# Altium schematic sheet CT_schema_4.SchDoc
size 511 x 385 mm
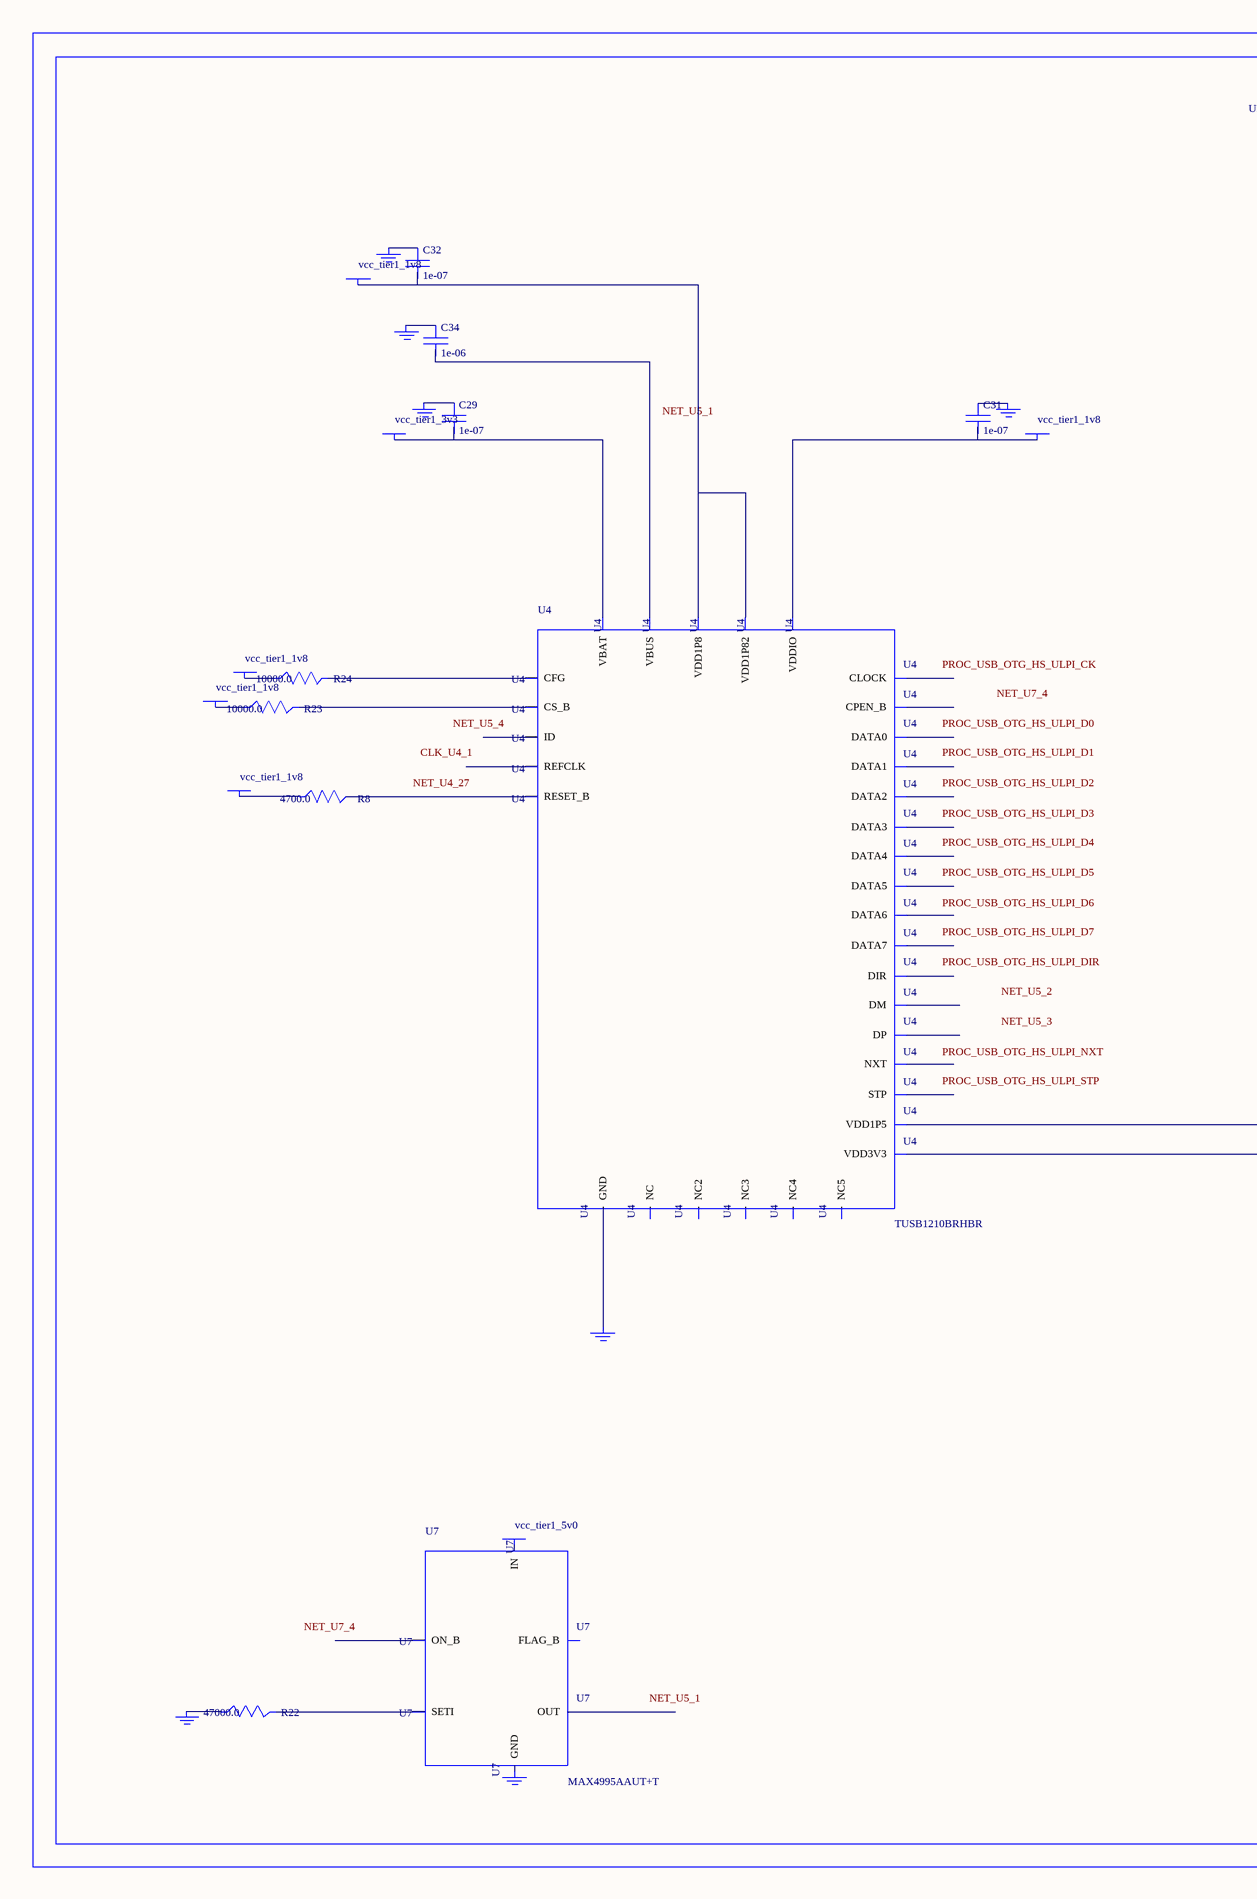
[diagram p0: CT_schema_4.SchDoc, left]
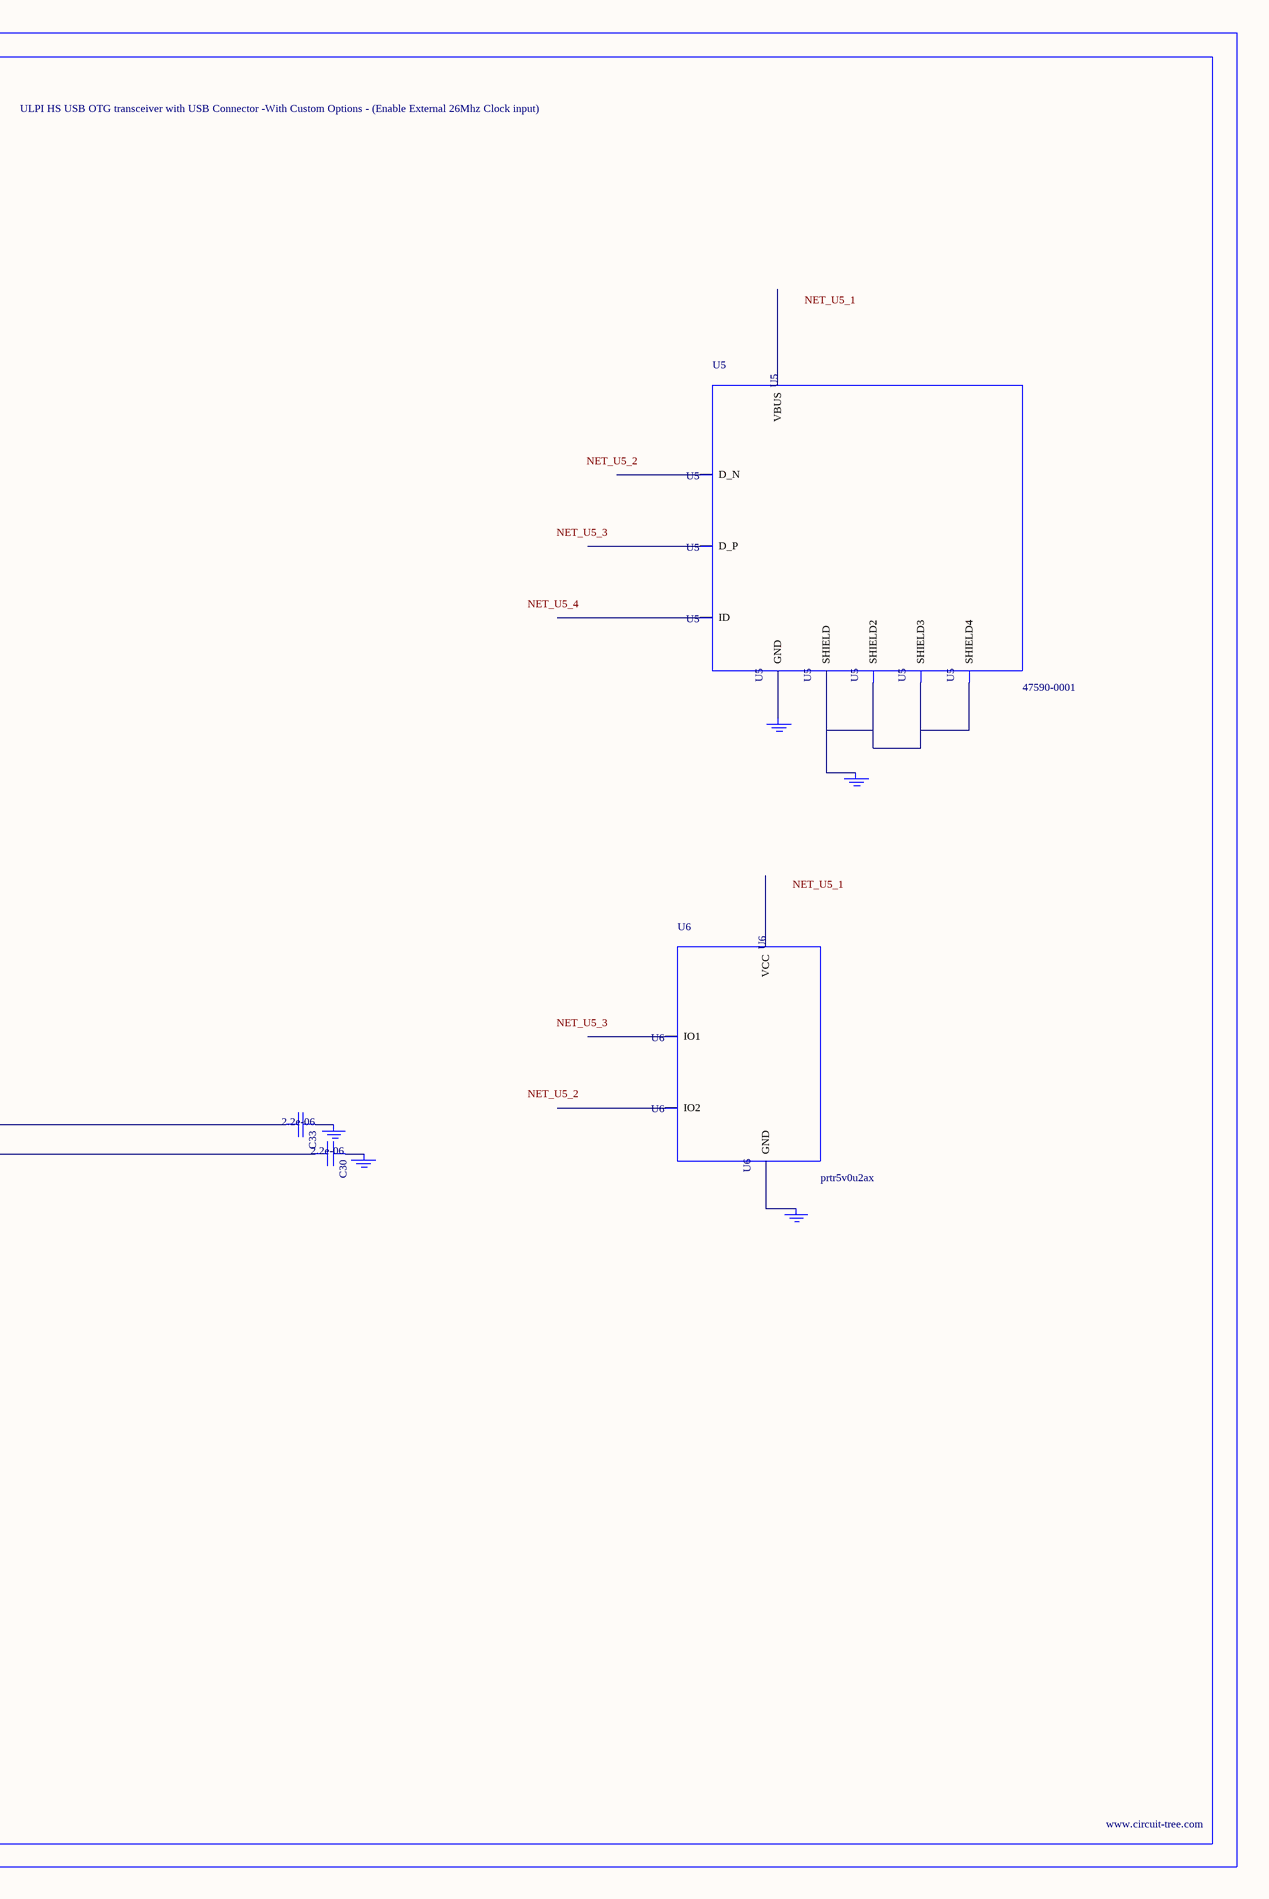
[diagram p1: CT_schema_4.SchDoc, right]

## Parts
BORDER3  (no value)
C29  1e-07  [C0402]
C30  2.2e-06  [C0603]
C31  1e-07  [C0402]
C32  1e-07  [C0402]
C33  2.2e-06  [C0603]
C34  1e-06  [C0603]
GND_INSTANCE_3_0  (no value)
GND_INSTANCE_3_1  (no value)
GND_INSTANCE_3_2  (no value)
GND_INSTANCE_3_3  (no value)
GND_INSTANCE_3_4  (no value)
GND_INSTANCE_3_5  (no value)
GND_INSTANCE_3_6  (no value)
GND_INSTANCE_3_7  (no value)
GND_INSTANCE_3_8  (no value)
GND_INSTANCE_3_9  (no value)
GND_INSTANCE_3_10  (no value)
GND_INSTANCE_3_11  (no value)
POWER_INSTANCE_3_0  vcc_tier1_1v8
POWER_INSTANCE_3_1  vcc_tier1_1v8
POWER_INSTANCE_3_2  vcc_tier1_3v3
POWER_INSTANCE_3_3  vcc_tier1_1v8
POWER_INSTANCE_3_4  vcc_tier1_1v8
POWER_INSTANCE_3_5  vcc_tier1_1v8
POWER_INSTANCE_3_6  vcc_tier1_5v0
R8  4700.0  [R0603]
R22  47000.0  [R0603]
R23  10000.0  [R0603]
R24  10000.0  [R0603]
U4  TUSB1210BRHBR  [RHB32_3P45X3P45]
U5  47590-0001  [MICRO_USB_AB]
U6  prtr5v0u2ax  [SOT143B]
U7  MAX4995AAUT+T  [SOT-23-6]

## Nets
NetC29_1: C29.1 GND_INSTANCE_3_2.0(GND)
NetC29_2: C29.2 POWER_INSTANCE_3_2.0(PWR) U4.21(VBAT)
NetC30_1: C30.1 GND_INSTANCE_3_1.0(GND)
NetC30_2: C30.2 U4.20(VDD3V3)
NetC31_1: C31.1 GND_INSTANCE_3_5.0(GND)
NetC31_2: C31.2 POWER_INSTANCE_3_4.0(PWR) U4.32(VDDIO)
NetC32_1: C32.1 GND_INSTANCE_3_4.0(GND)
NetC32_2: C32.2 POWER_INSTANCE_3_3.0(PWR) U4.28(VDD1P8) U4.30(VDD1P82)
NetC33_1: C33.1 GND_INSTANCE_3_0.0(GND)
NetC33_2: C33.2 U4.12(VDD1P5)
NetC34_1: C34.1 GND_INSTANCE_3_3.0(GND)
NetC34_2: C34.2 U4.22(VBUS)
NetGND_INSTANCE_3_6_0: GND_INSTANCE_3_6.0(GND) U4.33(GND)
NetGND_INSTANCE_3_7_0: GND_INSTANCE_3_7.0(GND) U5.6(SHIELD) U5.7(SHIELD2) U5.8(SHIELD3) U5.9(SHIELD4)
NetGND_INSTANCE_3_8_0: GND_INSTANCE_3_8.0(GND) U5.5(GND)
NetGND_INSTANCE_3_9_0: GND_INSTANCE_3_9.0(GND) U6.1(GND)
NetGND_INSTANCE_3_10_0: GND_INSTANCE_3_10.0(GND) R22.1
NetPOWER_INSTANCE_3_0_0: POWER_INSTANCE_3_0.0(PWR) R23.1
NetPOWER_INSTANCE_3_1_0: POWER_INSTANCE_3_1.0(PWR) R24.1
NetPOWER_INSTANCE_3_5_0: POWER_INSTANCE_3_5.0(PWR) R8.1
NetR8_2: R8.2 U4.27(RESET_B)
NetR22_2: R22.2 U7.3(SETI)
NetR23_2: R23.2 U4.11(CS_B)
NetR24_2: R24.2 U4.14(CFG)

Not connected (* = marked no-connect by the designer): GND_INSTANCE_3_11 0(GND); POWER_INSTANCE_3_6 0(PWR); U4 1(REFCLK) 2(NXT) 3(DATA0) 4(DATA1) 5(DATA2) 6(DATA3) 7(DATA4) 8(NC) 9(DATA5) 10(DATA6) 13(DATA7) 15(NC2) 16(NC3) 17(CPEN_B) 18(DP) 19(DM) 23(ID) 24(NC4) 25(NC5) 26(CLOCK) 29(STP) 31(DIR); U5 1(VBUS) 2(D_N) 3(D_P) 4(ID); U6 2(IO1) 3(IO2) 4(VCC); U7 1(OUT) 2(GND) 4(ON_B) 5(IN) 6(FLAG_B)

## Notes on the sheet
- Labels drawn without touching a wire or pin: CLK_U4_1, NET_U4_27, NET_U5_1, NET_U5_2, NET_U5_3, NET_U5_4, NET_U7_4, PROC_USB_OTG_HS_ULPI_CK, PROC_USB_OTG_HS_ULPI_D0, PROC_USB_OTG_HS_ULPI_D1, PROC_USB_OTG_HS_ULPI_D2, PROC_USB_OTG_HS_ULPI_D3, PROC_USB_OTG_HS_ULPI_D4, PROC_USB_OTG_HS_ULPI_D5, PROC_USB_OTG_HS_ULPI_D6, PROC_USB_OTG_HS_ULPI_D7, PROC_USB_OTG_HS_ULPI_DIR, PROC_USB_OTG_HS_ULPI_NXT, PROC_USB_OTG_HS_ULPI_STP

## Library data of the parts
BORDER3 = BORDER_PAGE3
C29 C31 C32 = C0402C104K3RACTU
C30 C33 = C0603C225K8RACTU
C34 = C0603C105K3RACTU
GND_INSTANCE_3_0-GND_INSTANCE_3_11 = GND
POWER_INSTANCE_3_0-POWER_INSTANCE_3_6 = PWR
R8 = RC0603JR-074K7L
R22 = RC0603JR-0747KL
R23 R24 = RC0603JR-0710KL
